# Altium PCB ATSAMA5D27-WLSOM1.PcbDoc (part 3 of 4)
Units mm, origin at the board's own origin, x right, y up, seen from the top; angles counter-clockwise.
Board outline 40.8 x 40.8 mm, 6 copper layers (L1 - Top, L2 - GND, L3 - Signal, L4 - Signal, L5 - PWR, L6 - Bottom), stack 1.144 mm thick; 196 components, 221 nets, 1038 pads, 713 vias.
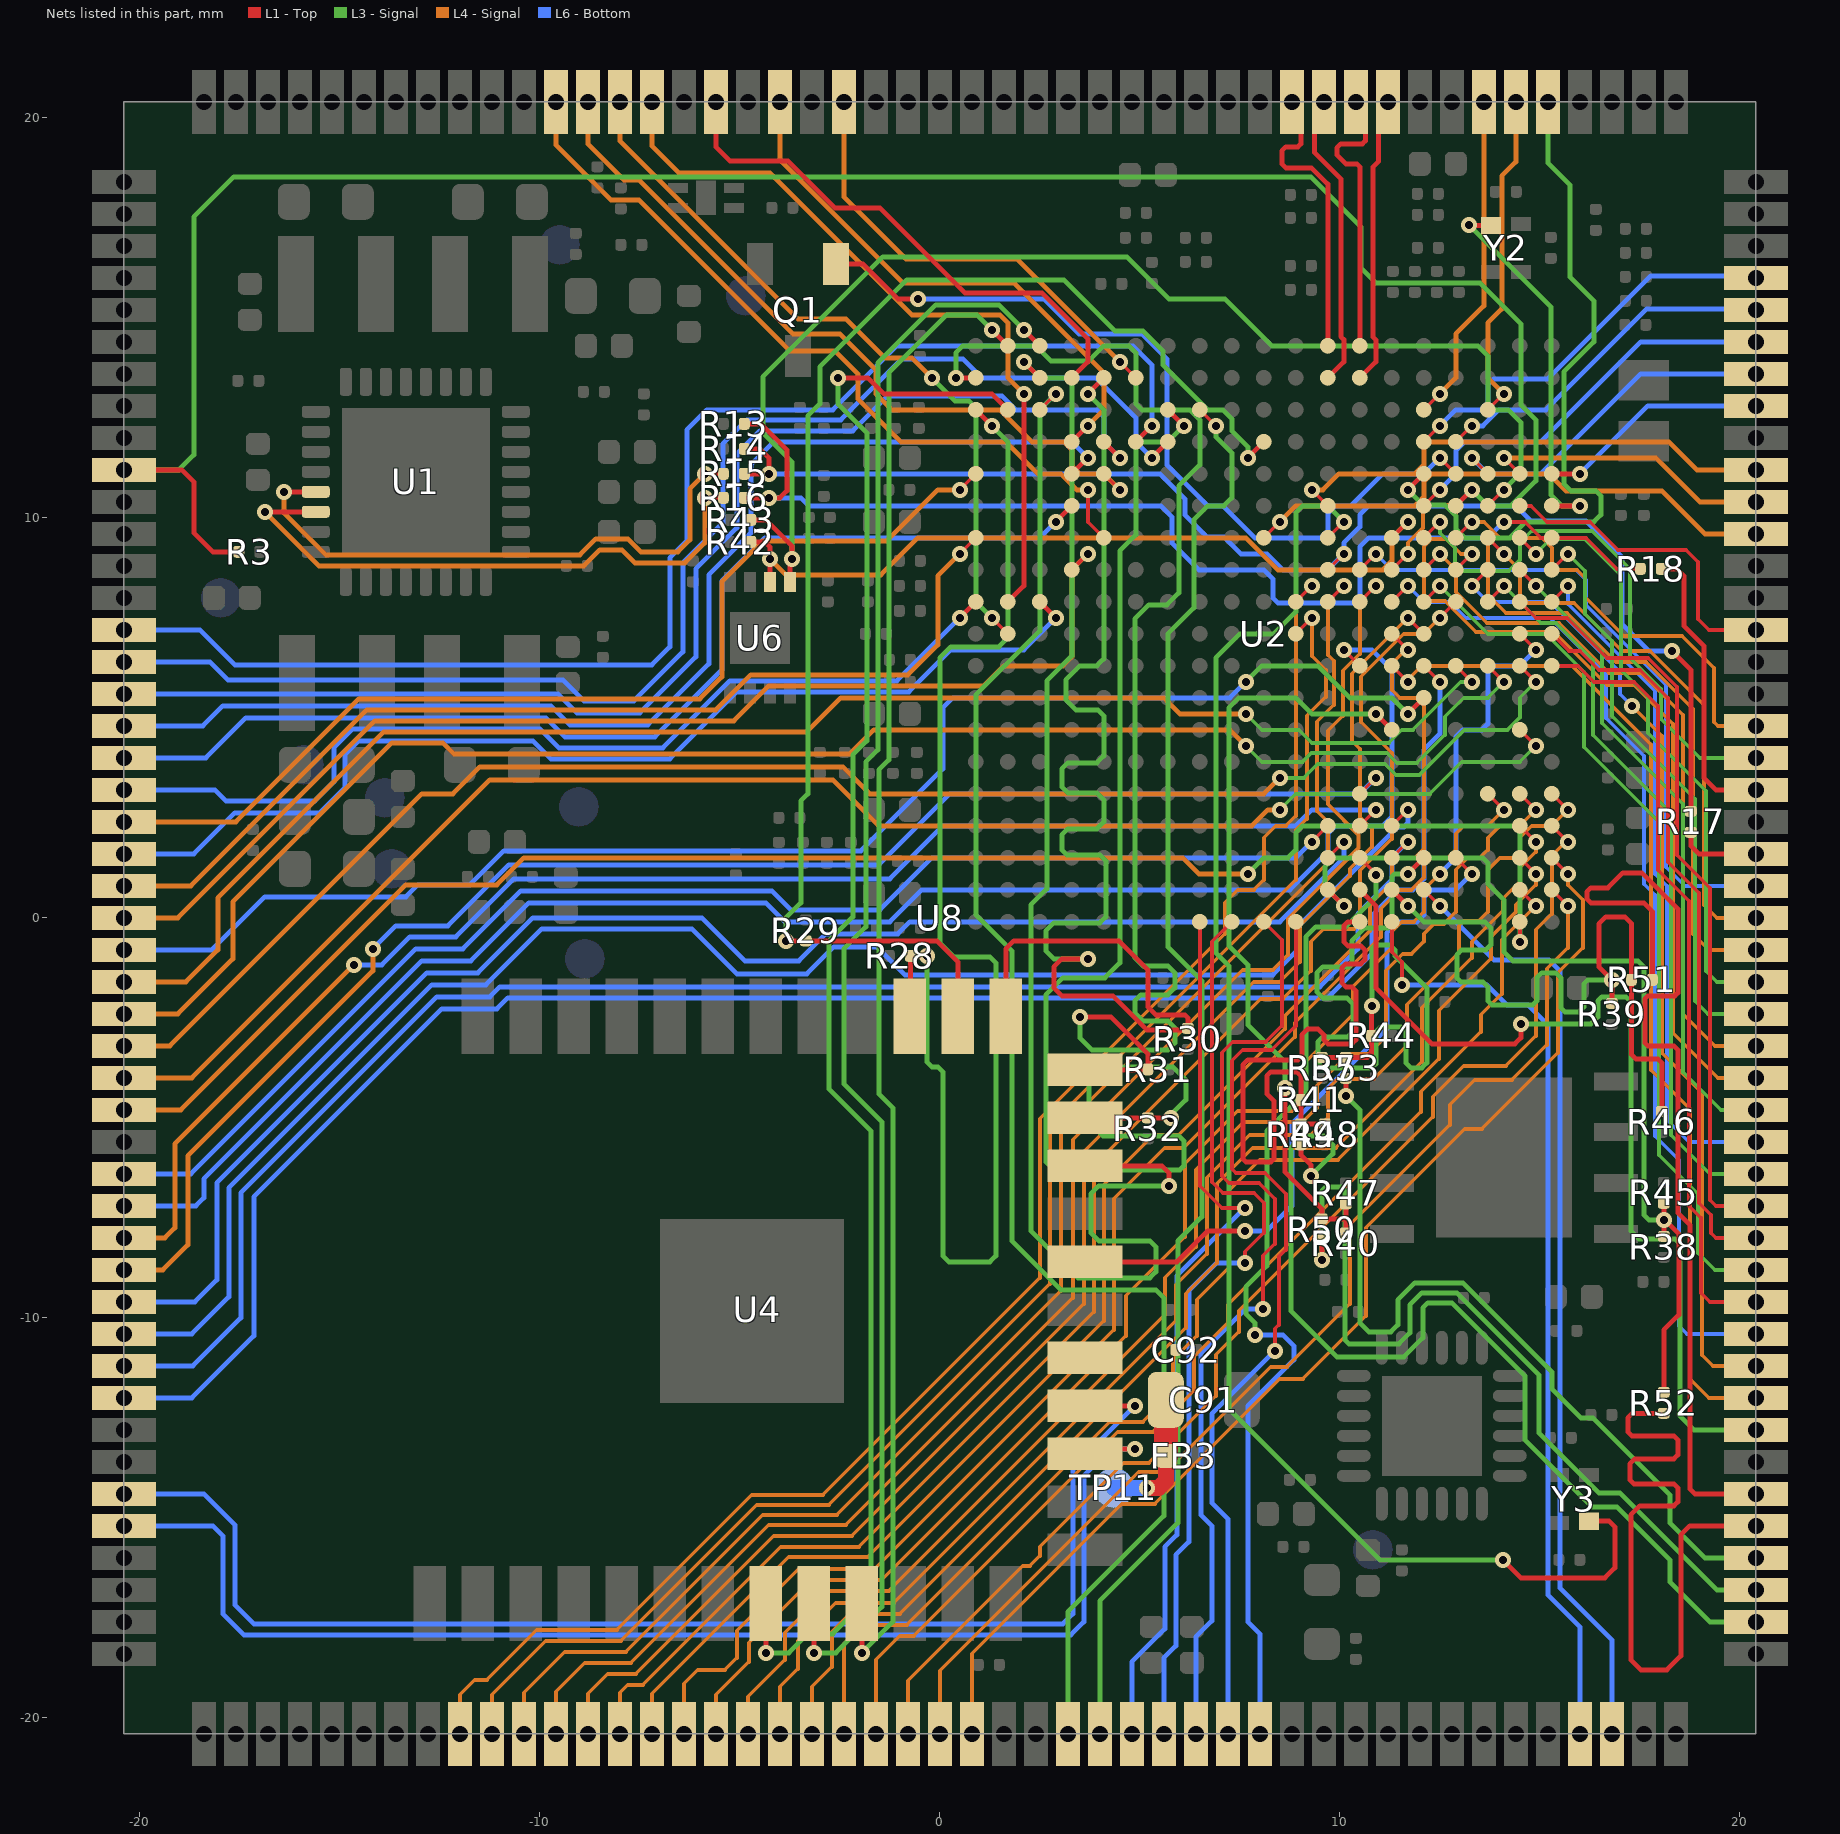
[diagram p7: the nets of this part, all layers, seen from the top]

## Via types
v1: diameter 0.4, hole 0.2, L1 - Top to L6 - Bottom, 680 vias
v2: diameter 0.4, hole 0.2, L1 - Top to L6 - Bottom, tented both sides, 17 vias
v3: diameter 0.4, hole 0.2, L1 - Top to L6 - Bottom, tented bottom, 16 vias

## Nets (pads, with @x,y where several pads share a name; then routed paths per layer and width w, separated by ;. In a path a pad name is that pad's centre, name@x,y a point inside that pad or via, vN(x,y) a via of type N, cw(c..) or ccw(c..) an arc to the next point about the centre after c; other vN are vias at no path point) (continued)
PA9: U2.V16 U8.172 | length 13.6
  L1 - Top w0.125: U8.172@-5.6,20.4 -5.6,19.275 -5.25,18.925 -3.8,18.925 -2.625,17.75 -1.5,17.75 0.625,15.625 2.55,15.625 3.7,14.475 3.7,13.9 U2.V16@3.3,13.5
PA10: U2.V14 U8.168 | length 11.5
  L1 - Top w0.1: v1(4.5,13.9) U2.V14@4.9,13.5
  L4 - Signal w0.125: U8.168@-2.4,20.4 -2.4,18.025 -0.85,16.475 1.925,16.475 v1(4.5,13.9)
PA11: U2.L18 U8.174 | length 19.1
  L1 - Top w0.125: U2.L18@1.7,7.9 2.1,8.3 v1(2.1,13.1)
  L4 - Signal w0.125: U8.174@-7.2,20.35 -7.2,19.3 -6.525,18.625 -4.25,18.625 -0.7,15.075 1.5,15.075 1.7,14.875 1.7,13.5 v1(2.1,13.1)
PA12: U2.T16 U8.170 | length 13.8
  L1 - Top w0.125: U2.T16@3.3,11.9 v1(3.7,12.3)
  L4 - Signal w0.125: U8.170@-4,20.4 -4,18.95 -0.925,15.875 1.85,15.875 4.1,13.625 4.1,12.7 v1(3.7,12.3)
PA13: U2.K18 U8.175 | length 18.6
  L1 - Top w0.1: v1(1.3,7.5) U2.K18@1.7,7.1
  L3 - Signal w0.125: v1(-0.2,13.5) 0.375,12.925 0.725,12.925 0.9,12.75 0.9,7.9 v1(1.3,7.5)
  L4 - Signal w0.125: U8.175@-8,20.4 -8,19.425 -3.55,14.975 -2.35,14.975 -1.375,14 -0.7,14 v1(-0.2,13.5)
PA14: U2.R19 U8.21 | length 26.3
  L1 - Top w0.1: v1(0.5,10.7) U2.R19@0.9,11.1
  L4 - Signal w0.125: U8.21@-20.4,2.4 -17.6,2.4 -14.525,5.475 -6,5.475 -5.45,6.025 -5.45,8.4 -4.425,9.425 -1.325,9.425 -0.05,10.7 v1(0.5,10.7)
PA15: U2.L17 U8.22 | length 27.2
  L1 - Top w0.125: U2.L17@2.5,7.9 v1(2.9,7.5)
  L6 - Bottom w0.125: U8.22@-20.4,1.6 -18.65,1.6 -17.625,2.625 -15.5,2.625 -14.875,3.25 -14.875,4.075 -14.525,4.425 -10.175,4.425 -9.725,3.975 -6.75,3.975 -5.075,5.65 -0.775,5.65 0.275,6.7 2.1,6.7 v1(2.9,7.5)
PA16: U2.N19 U8.23 | length 25.9
  L1 - Top w0.1: v1(0.5,9.1) U2.N19@0.9,9.5
  L4 - Signal w0.125: U8.23@-20.4,0.8 -18.725,0.8 -14.325,5.2 -5.6,5.2 -4.725,6.075 -0.8,6.075 -0.05,6.825 -0.05,8.55 v1(0.5,9.1)
PA17: U2.M16 U8.24 | length 29.7
  L1 - Top w0.1: U2.M16@3.3,8.7 v1(3.7,9.1)
  L4 - Signal w0.125: U8.24@-20.4,0 -19.05,0 -14.125,4.925 -5.15,4.925 -4.275,5.8 1.1,5.8 1.6,6.3 3.075,6.3 3.3,6.525 3.3,8.7 v1(3.7,9.1)
PA30: U2.U12 U8.76 | length 35.7
  L1 - Top w0.1: U2.U12@6.5,12.7 v1(6.9,12.3)
  L3 - Signal w0.125: U8.76@4,-20.4 4,-17.075 5.95,-15.125 5.95,-8.075 6.55,-7.475 6.55,-1.575 5.7,-0.725 5.7,7.1 6.35,7.75 6.35,9.95 6.7,10.3 7.1,10.3 7.3,10.5 7.3,11.625 6.9,12.025 v1(6.9,12.3)
PA31: U2.U17 U8.75 | length 39.2
  L1 - Top w0.1: U2.U17@2.5,12.7 v1(2.9,13.1)
  L3 - Signal w0.125: v1(2.9,13.1) 2.5,12.7 2.5,7.175 0.9,5.575 0.9,0.075 1.8,-0.825 1.8,-8.075 3.025,-9.3 5.4,-9.3 5.6,-9.5 5.6,-14.95 3.2,-17.35 U8.75@3.2,-20.4
PB0: U2.C7 U8.81 | length 25.4
  L1 - Top w0.1: U2.C7@10.5,1.5 10.9,1.1 v1(10.9,1.075)
  L3 - Signal w0.125: v1(7.875,-10.425) 7.875,-10.125 7.65,-9.9 7.65,-9.225 8.175,-8.7 8.175,-5.325 9.15,-4.35 9.15,-0.475 9.4,-0.225 10.15,-0.225 10.9,0.525 v1(10.9,1.075)
  L6 - Bottom w0.125: v1(7.875,-10.425) 8.575,-10.425 8.85,-10.7 8.85,-11.05 7.7,-12.2 7.7,-17.6 8,-17.9 U8.81@8,-20.4
PB1: U2.A9 U8.80 | length 23.3
  L1 - Top w0.1: v1(8.375,-10.825) 8.375,-10.275 8.475,-10.175 8.475,-8.475 8.65,-8.3 8.65,-6.9 8.125,-6.375 7.4,-6.375 7.3,-6.275 7.3,-3.575 7.575,-3.3 8.3,-3.3 8.9,-2.7 U2.A9@8.9,-0.1
  L6 - Bottom w0.125: U8.80@7.2,-20.4 7.2,-15.025 6.8,-14.625 6.8,-12.4 v1(8.375,-10.825)
PB2: U2.A10 U8.79 | length 23.9
  L1 - Top w0.1: v1(8.075,-9.775) 8.075,-8.45 8.375,-8.15 8.375,-7.025 7.975,-6.625 7.225,-6.625 7.05,-6.45 7.05,-3.375 7.325,-3.1 8.15,-3.1 8.55,-2.7 8.55,-0.55 U2.A10@8.1,-0.1
  L6 - Bottom w0.125: U8.79@6.4,-20.4 6.4,-17.975 6.8,-17.575 6.8,-15.2 6.525,-14.925 6.525,-10.9 7.65,-9.775 v1(8.075,-9.775)
PB3: U2.A11 U8.78 | length 22.9
  L1 - Top w0.1: U2.A11@7.3,-0.1 6.8,-0.6 6.8,-6.6 7.075,-6.875 7.85,-6.875 8.1,-7.125 8.1,-7.875 7.625,-8.35 v1(7.625,-8.625)
  L6 - Bottom w0.125: U8.78@5.6,-20.4 5.6,-18.5 5.9,-18.2 5.9,-15.925 6.225,-15.6 6.225,-9.325 6.925,-8.625 v1(7.625,-8.625)
PB4: U2.A12 U8.77 | length 22.3
  L1 - Top w0.1: U2.A12@6.5,-0.1 6.5,-0.617 6.5,-6.7 7.05,-7.25 v1(7.625,-7.25)
  L6 - Bottom w0.125: U8.77@4.8,-20.4 4.8,-18.6 5.625,-17.775 5.625,-15.725 5.925,-15.425 5.925,-8.95 v1(7.625,-7.25)
PB11: U2.B5 U8.92 | length 23.9
  L1 - Top w0.1: U2.B5@12.1,0.7 v1(12.5,0.3)
  L6 - Bottom w0.125: v1(12.5,0.3) 13.85,-1.05 15.225,-1.05 15.5,-1.325 15.5,-16.75 16.8,-18.05 U8.92@16.8,-20.4
PB12: U2.A6 U8.91 | length 23.8
  L1 - Top w0.1: U2.A6@11.3,-0.1 11.3,-0.85 11.55,-1.1 v1(11.55,-1.675)
  L6 - Bottom w0.125: v1(11.55,-1.675) 13.675,-1.675 14.175,-2.175 14.7,-2.175 15.2,-2.675 15.2,-16.925 16,-17.725 U8.91@16,-20.4
PB26: U2.G2 U8.29 | length 40.3
  L1 - Top w0.1: U2.G2@14.5,4.7 v1(14.9,4.3)
  L3 - Signal w0.1: v1(8.5,2.7) 8.9,3.1 12.25,3.1 13.05,3.9 14.5,3.9 v1(14.9,4.3)
  L4 - Signal w0.125: U8.29@-20.4,-4 -18.7,-4 -11.25,3.45 -2.675,3.45 -1.525,2.3 7.8,2.3 8.2,2.7 v1(8.5,2.7)
PB27: U2.H5 U8.25 | length 37
  L1 - Top w0.125: v1(11.7,5.1) U2.H5@12.1,5.5
  L3 - Signal w0.125: v1(7.65,5.9) 8.05,6.3 9.45,6.3 10.25,5.5 11.3,5.5 v1(11.7,5.1)
  L6 - Bottom w0.125: U8.25@-20.4,-0.8 -18.2,-0.8 -16.875,0.525 -13.35,0.525 -13.05,0.825 -11.75,0.825 -10.9,1.675 -1.975,1.675 0.075,3.725 0.075,5.25 0.325,5.5 7.25,5.5 v1(7.65,5.9)
PB28: U2.J2 U8.28 | length 40.7
  L1 - Top w0.1: U2.J2@14.5,6.3 v1(14.9,5.9)
  L3 - Signal w0.1: v1(8.5,3.5) 9.1,3.5 9.45,3.85 11.125,3.85 11.4,3.575 11.992,3.575 13.117,4.7 14.195,4.7 14.5,5.005 14.5,5.5 v1(14.9,5.9)
  L4 - Signal w0.125: U8.28@-20.4,-3.2 -19.25,-3.2 -12.95,3.1 -12.175,3.1 -11.5,3.775 -2.425,3.775 -1.75,3.1 8.1,3.1 v1(8.5,3.5)
PB29: U2.J3 U8.27 | length 40.7
  L1 - Top w0.1: U2.J3@13.7,6.3 v1(14.1,5.9)
  L3 - Signal w0.1: v1(7.65,4.3) 8.05,3.9 9.067,3.9 9.292,4.125 11.175,4.125 11.425,3.875 11.925,3.875 12.625,4.575 12.625,5.025 13.1,5.5 13.7,5.5 v1(14.1,5.9)
  L4 - Signal w0.125: U8.27@-20.4,-2.4 -19.05,-2.4 -17.675,-1.025 -17.675,0.4 -13.7,4.375 -12.425,4.375 -12.15,4.1 -2.25,4.1 -1.65,4.7 7.25,4.7 v1(7.65,4.3)
PB30: U2.A2 U8.30 | length 41.8
  L1 - Top w0.1: v1(14.5,-0.6) U2.A2@14.5,-0.1
  L3 - Signal w0.125: v1(7.7,1.1) 8.1,1.5 8.7,1.5 8.9,1.7 8.9,2.125 9.075,2.3 14.325,2.3 14.5,2.125 v1(14.5,-0.6)
  L4 - Signal w0.125: U8.30@-20.4,-4.8 -18.975,-4.8 -13.35,0.825 -11.075,0.825 -10.4,1.5 6.075,1.5 6.475,1.1 v1(7.7,1.1) v1@7.75,1.1
PB31: U2.J4 U8.26 | length 39.1
  L1 - Top w0.1: U2.J4@12.9,6.3 v1(13.3,5.9)
  L3 - Signal w0.1: v1(7.65,5.1) 8.05,4.7 8.975,4.7 9.3,4.375 11.225,4.375 11.55,4.7 11.825,4.7 13.025,5.9 v1(13.3,5.9)
  L4 - Signal w0.125: U8.26@-20.4,-1.6 -18.85,-1.6 -18.05,-0.8 -18.05,0.5 -13.9,4.65 -3.325,4.65 -2.475,5.5 5.6,5.5 6,5.1 v1(7.65,5.1)
PC0: U2.T14 U8.15 | length 34.6
  L1 - Top w0.125: U2.T14@4.9,11.9 v1(5.3,12.3)
  L6 - Bottom w0.125: U8.15@-20.4,7.2 -18.5,7.2 -17.625,6.325 -7.2,6.325 -6.75,6.775 -6.75,9 -6.325,9.425 -6.325,12.2 -5.825,12.7 -2.675,12.7 -1.075,14.3 4.825,14.3 5.3,13.825 v1(5.3,12.3)
PC1: U2.R16 U8.18 | length 30.7
  L1 - Top w0.125: U2.R16@3.3,11.1 v1(3.7,11.5)
  L6 - Bottom w0.125: U8.18@-20.2,5 U8.18@-20.4,4.8 -18.425,4.8 -17.925,5.3 -9.725,5.3 -9.25,4.825 -7.3,4.825 -5.775,6.35 -5.775,8.575 -4.725,9.625 -4.725,11.325 -4.15,11.9 3.3,11.9 v1(3.7,11.5)
PC2: U2.T15 U8.17 | length 32.3
  L1 - Top w0.125: U2.T15@4.1,11.9 v1(4.5,11.5)
  L6 - Bottom w0.125: U8.17@-20.4,5.6 -9.55,5.6 -9.075,5.125 -7.5,5.125 -6.1,6.525 -6.1,8.725 -5.075,9.75 -5.075,11.6 -4.5,12.175 -2.175,12.175 -1.3,13.05 1.55,13.05 1.9,12.7 3.925,12.7 4.1,12.525 4.1,11.9 v1(4.5,11.5)
PC3: U2.T13 U8.16 | length 34
  L1 - Top w0.125: v1(5.3,11.5) U2.T13@5.7,11.9
  L6 - Bottom w0.125: U8.16@-20.4,6.4 -18.25,6.4 -17.8,5.95 -9.425,5.95 -8.9,5.425 -7.65,5.425 -6.425,6.65 -6.425,8.875 -5.425,9.875 -5.425,11.85 -4.825,12.45 -2.475,12.45 -0.95,13.975 0.575,13.975 1.05,13.5 3.9,13.5 4.9,12.5 4.9,11.9 v1(5.3,11.5)
PC4: U2.P16 U8.19 | length 28
  L1 - Top w0.125: v1(2.9,9.9) U2.P16@3.3,10.3
  L6 - Bottom w0.125: U8.19@-20.4,4 -18.35,4 -17.35,5 -9.85,5 -9.375,4.525 -7.125,4.525 -5.45,6.2 -5.45,8.425 -4.375,9.5 2.5,9.5 v1(2.9,9.9)
PC5: U2.L19 U8.20 | length 24.4
  L1 - Top w0.125: v1(0.5,7.5) U2.L19@0.9,7.9
  L6 - Bottom w0.125: U8.20@-20.4,3.2 -18.125,3.2 -17.85,2.925 -15.625,2.925 -15.15,3.4 -15.15,4.25 -14.675,4.725 -10,4.725 -9.525,4.25 -6.925,4.25 -5.25,5.925 -1.075,5.925 v1(0.5,7.5)
PC6: U2.R15 U8.176 | length 19.1
  L1 - Top w0.1: U2.R15@4.1,11.1 v1(4.5,10.7)
  L4 - Signal w0.125: U8.176@-8.8,20.4 -8.8,19.35 -7.9,18.45 -7.525,18.45 -3.675,14.6 -2.5,14.6 -1.6,13.7 -1.6,13.1 -1.2,12.7 1.5,12.7 2.3,11.9 3.1,11.9 3.3,11.7 3.3,11.3 3.5,11.1 4.1,11.1 v1(4.5,10.7)
PC7: U2.N15 U8.177 | length 19.7
  L1 - Top w0.1: v1(3.7,10.7) 3.7,9.9 U2.N15@4.1,9.5
  L4 - Signal w0.125: U8.177@-9.6,20.4 -9.6,19.325 -8.225,17.95 -7.525,17.95 -3.75,14.175 -2.625,14.175 -2.05,13.6 -2.05,12.975 -0.975,11.9 1.65,11.9 2.45,11.1 3.025,11.1 3.425,10.7 v1(3.7,10.7)
PC9: U2.B2 U8.69 | length 28.8
  L1 - Top w0.1: U2.B2@14.5,0.7 v1(14.9,0.3)
  L4 - Signal w0.1: U8.69@-1.6,-20.4 -1.6,-18.55 -1,-17.95 -0.65,-17.95 4.45,-12.85 5.325,-12.85 6.35,-11.825 6.35,-10.975 7.2,-10.125 7.2,-9.675 12.025,-4.85 12.025,-4.35 13.525,-2.85 13.525,-2.425 14.05,-1.9 14.05,-0.55 v1(14.9,0.3)
PC10: U2.K5 U8.60 | length 39.3
  L1 - Top w0.1: v1(11.7,7.5) U2.K5@12.1,7.1
  L4 - Signal w0.1: U8.60@-8.8,-20.4 -8.8,-19.4 -8.3,-18.9 -7.6,-18.9 -4.15,-15.45 -2.2,-15.45 3.6,-9.65 3.6,-5.85 7.85,-1.6 8.5,-1.6 9,-1.1 9,-0.2 10.25,1.05 10.25,1.225 10.8,1.775 10.8,2.225 10.5,2.525 10.5,4.225 10.3,4.425 10.3,6.1 v1(11.7,7.5)
PC11: U2.C2 U8.68 | length 31.5
  L1 - Top w0.1: U2.C2@14.5,1.5 v1(14.9,1.1)
  L4 - Signal w0.1: U8.68@-2.4,-20.4 -2.4,-18.15 -1.925,-17.675 -0.825,-17.675 4.25,-12.6 5.075,-12.6 5.825,-11.85 5.825,-11.05 6.425,-10.45 6.425,-9.55 7.225,-8.75 7.225,-6.825 8,-6.05 9.95,-6.05 12.475,-3.525 12.475,-2.325 13.775,-1.025 13.775,-0.486 14.4,0.139 14.4,0.325 14.9,0.825 v1(14.9,1.1)
PC12: U2.D2 U8.67 | length 32.3
  L1 - Top w0.1: U2.D2@14.5,2.3 v1(14.9,1.9)
  L4 - Signal w0.1: U8.67@-3.2,-20.4 -3.2,-19.225 -2.7,-18.725 -2.7,-17.85 -2.25,-17.4 -1,-17.4 6.15,-10.25 6.15,-9.4 6.925,-8.625 6.925,-6.65 7.825,-5.75 9.9,-5.75 12.05,-3.6 12.05,-2.25 13.3,-1 13.3,-0.6 14.075,0.175 14.075,0.475 14.5,0.9 14.5,1.25 14.9,1.65 v1(14.9,1.9)
PC13: U2.K2 U8.64 | length 38.8
  L1 - Top w0.1: U2.K2@14.5,7.1 v1(14.9,6.7)
  L4 - Signal w0.1: U8.64@-5.6,-20.4 -5.6,-19.425 -4.775,-18.6 -4.775,-18.125 -3.2,-16.55 -1.45,-16.55 4.65,-10.45 4.65,-9.45 6.125,-7.975 6.125,-6.15 7.45,-4.825 8.8,-4.825 9.15,-4.475 9.15,-3.6 10.325,-2.425 10.325,-1.725 11.3,-0.75 11.3,-0.35 11.55,-0.1 11.85,-0.1 12.1,0.15 12.1,0.7 v1(12.5,1.1)
  L6 - Bottom w0.125: v1(12.5,1.1) 12.9,1.5 12.9,4.525 13.075,4.7 13.55,4.7 13.7,4.85 13.7,6.175 13.825,6.3 14.5,6.3 v1(14.9,6.7)
PC14: U2.K6 U8.62 | length 38.2
  L1 - Top w0.1: U2.K6@11.3,7.1 v1(11.7,6.7)
  L4 - Signal w0.1: U8.62@-7.2,-20.4 -7.2,-19.4 -3.775,-15.975 -1.8,-15.975 4.1,-10.075 4.1,-6.675 5.35,-5.425 5.975,-5.425 8.625,-2.775 8.625,-2.459 10.75,-0.334 10.75,0.325 11.3,0.875 11.3,1.375 11.425,1.5 11.875,1.5 12.1,1.725 12.1,5.3 11.9,5.5 11.5,5.5 11.3,5.7 11.3,6.35 11.65,6.7 v1(11.7,6.7)
PC15: U2.B1 U8.71 | length 28.9
  L1 - Top w0.1: U2.B1@15.3,0.7 v1(15.7,0.3)
  L4 - Signal w0.1: U8.71@0,-20.4 0,-18.825 4.975,-13.85 5.65,-13.85 8.275,-11.225 8.675,-11.225 10.25,-9.65 10.25,-7.675 12.75,-5.175 12.75,-4.675 13.375,-4.05 14.3,-4.05 15.175,-3.175 15.175,-1.275 15.7,-0.75 v1(15.7,0.3)
PC16: U2.K9 U8.57 | length 39.4
  L1 - Top w0.1: U2.K9@8.9,7.1 v1(9.3,7.5)
  L4 - Signal w0.1: U8.57@-11.2,-20.4 -11.2,-19.425 -9.85,-18.075 -7.975,-18.075 -4.575,-14.675 -2.775,-14.675 2.75,-9.15 2.75,-5.2 8.9,0.95 8.9,2.2 9.175,2.475 9.175,5.05 9.65,5.525 9.65,6.2 9.3,6.55 v1(9.3,7.5)
PC17: U2.C1 U8.72 | length 29.6
  L1 - Top w0.1: U2.C1@15.3,1.5 v1(15.7,1.1)
  L4 - Signal w0.1: U8.72@0.8,-20.4 0.8,-18.4 4.55,-14.65 5.375,-14.65 8.5,-11.525 9.075,-11.525 10.65,-9.95 10.65,-7.75 13.125,-5.275 13.55,-5.275 15.45,-3.375 15.45,-1.375 16.075,-0.75 16.075,0.45 15.7,0.825 v1(15.7,1.1)
PC18: U2.L9 U8.56 | length 40.9
  L1 - Top w0.1: U2.L9@8.9,7.9 v1(9.3,8.3)
  L4 - Signal w0.1: U8.56@-12,-20.4 -12,-19.425 -11.625,-19.05 -11.325,-19.05 -10.075,-17.8 -8.075,-17.8 -4.7,-14.425 -2.925,-14.425 2.5,-9 2.5,-5.025 7.125,-0.4 7.125,0.375 7.45,0.7 7.85,0.7 8.1,0.95 8.1,2 8.4,2.3 8.65,2.3 8.9,2.55 8.9,7.9 v1(9.3,8.3)
PC19: U2.D1 U8.70 | length 30.8
  L1 - Top w0.1: U2.D1@15.3,2.3 v1(15.7,1.9)
  L4 - Signal w0.1: U8.70@-0.8,-20.4 -0.8,-19.075 2.075,-16.2 2.25,-16.2 2.5,-15.95 2.5,-15.725 4.6,-13.625 5.225,-13.625 6.9,-11.95 6.9,-10.925 7.475,-10.35 7.475,-9.825 12.325,-4.975 12.325,-4.475 13.1,-3.7 14.15,-3.7 14.9,-2.95 14.9,-0.3 15.3,0.1 15.3,1.55 15.65,1.9 v1(15.7,1.9)
PC20: U2.L8 U8.58 | length 40.1
  L1 - Top w0.1: U2.L8@9.7,7.9 v1(10.1,8.3)
  L4 - Signal w0.1: U8.58@-10.4,-20.4 -10.4,-19.375 -9.375,-18.35 -7.85,-18.35 -4.425,-14.925 -2.575,-14.925 3.025,-9.325 3.025,-5.3 9.7,1.375 9.7,2.4 9.425,2.675 9.425,4.9 9.85,5.325 9.85,6.425 9.7,6.575 9.7,7.9 v1(10.1,8.3)
PC21: U2.E3 U8.63 | length 34.7
  L1 - Top w0.1: U2.E3@13.7,3.1 v1(14.1,2.7)
  L4 - Signal w0.1: U8.63@-6.4,-20.4 -6.4,-19.15 -6.05,-18.8 -5.375,-18.8 -5.075,-18.5 -5.075,-17.825 -3.525,-16.275 -1.625,-16.275 4.35,-10.3 4.35,-7.025 5.625,-5.75 6.1,-5.75 8.875,-2.975 8.875,-2.625 11.025,-0.475 11.025,0.225 11.5,0.7 11.795,0.7 12.1,1.005 12.1,1.3 12.3,1.5 12.7,1.5 12.9,1.7 12.9,2.1 13.1,2.3 13.7,2.3 v1(14.1,2.7)
PC22: U2.E2 U8.65 | length 34.6
  L1 - Top w0.1: U2.E2@14.5,3.1 v1(14.9,2.7)
  L4 - Signal w0.1: U8.65@-4.8,-20.4 -4.8,-19.475 -3.875,-18.55 -3.875,-17.875 -2.825,-16.825 -1.275,-16.825 5.625,-9.925 5.625,-9 6.4,-8.225 6.4,-6.3 7.6,-5.1 9.075,-5.1 9.425,-4.75 9.425,-4.2 10.225,-3.4 10.725,-3.4 11.15,-2.975 11.15,-1.325 11.575,-0.9 11.795,-0.9 12.1,-0.595 12.1,-0.405 12.355,-0.15 12.6,-0.15 12.9,0.15 12.9,1.2 13.2,1.5 13.5,1.5 13.7,1.7 13.7,1.995 14.005,2.3 14.5,2.3 v1(14.9,2.7)
PC23: U2.L7 U8.59 | length 40.6
  L1 - Top w0.1: U2.L7@10.5,7.9 v1(10.9,8.3)
  L4 - Signal w0.1: U8.59@-9.6,-20.4 -9.6,-19.35 -8.875,-18.625 -7.725,-18.625 -4.275,-15.175 -2.35,-15.175 3.325,-9.5 3.325,-5.55 7.575,-1.3 8.334,-1.3 8.7,-0.934 8.7,-0.025 10.467,1.742 10.467,2.072 9.7,2.839 9.7,4.675 10.075,5.05 10.075,6.175 10.5,6.6 10.5,7.9 v1(10.9,8.3)
PC24: U2.E1 U8.66 | length 34.8
  L1 - Top w0.1: U2.E1@15.3,3.1 v1(15.7,2.7)
  L4 - Signal w0.1: U8.66@-4,-20.4 -4,-19.225 -3.55,-18.775 -3.55,-18.075 -2.6,-17.125 -1.15,-17.125 5.9,-10.075 5.9,-9.175 6.675,-8.4 6.675,-6.5 7.75,-5.425 9.275,-5.425 9.7,-5 9.7,-4.275 9.95,-4.025 10.85,-4.025 11.675,-3.2 11.675,-2.175 12.975,-0.875 12.975,-0.2 13.1,-0.075 13.475,-0.075 13.7,0.15 13.7,1.195 14.005,1.5 14.325,1.5 14.5,1.675 14.5,2 14.8,2.3 15.3,2.3 v1(15.7,2.7)
PC25: U2.L4 U8.61 | length 40
  L1 - Top w0.1: v1(12.5,7.5) U2.L4@12.9,7.9
  L4 - Signal w0.1: U8.61@-8,-20.4 -8,-19.375 -7.8,-19.175 -7.425,-19.175 -3.975,-15.725 -2.025,-15.725 3.85,-9.85 3.85,-6.2 8.025,-2.025 8.575,-2.025 9.275,-1.325 9.275,-0.6 9.6,-0.275 10.35,-0.275 10.5,-0.125 10.5,1.175 11.3,1.975 11.3,4.125 10.525,4.9 10.525,6.025 11.6,7.1 12.1,7.1 v1(12.5,7.5)
PC26: U2.D6 U8.37 | length 41.7
  L1 - Top w0.1: U2.D6@11.3,2.3 v1(11.7,2.7)
  L6 - Bottom w0.125: U8.37@-20.4,-10.4 -18.7,-10.4 -17.775,-9.475 -17.775,-6.75 -12.7,-1.675 -11.35,-1.675 -9.95,-0.275 -6.2,-0.275 -5.075,-1.4 -3.325,-1.4 -2.65,-0.725 -1.575,-0.725 -0.875,-1.425 8.325,-1.425 8.925,-0.825 8.925,-0.25 11.45,2.275 11.6,2.275 11.7,2.375 v1(11.7,2.7)
PC27: U2.E7 U8.35 | length 38.6
  L1 - Top w0.1: U2.E7@10.5,3.1 v1(10.9,3.5)
  L4 - Signal w0.125: U8.35@-20.4,-8.8 -19.425,-8.8 -18.8,-8.175 -18.8,-5.95 -14.175,-1.325 v1(-14.175,-0.775)
  L6 - Bottom w0.125: v1(-14.175,-0.775) -13.6,-0.2 -12.3,-0.2 -10.775,1.325 -1.525,1.325 0.25,3.1 10.5,3.1 v1(10.9,3.5)
PC28: U2.J5 U8.39 | length 46.1
  L1 - Top w0.1: U2.J5@12.1,6.3 v1(12.5,5.9)
  L6 - Bottom w0.125: U8.39@-20.4,-12 -18.7,-12 -17.15,-10.45 -17.15,-6.975 -12.45,-2.275 -11.075,-2.275 -10.8,-2 9.7,-2 10.8,-0.9 10.8,0.05 11.45,0.7 11.825,0.7 12.1,0.975 12.1,4.2 12.5,4.6 v1(12.5,5.9)
PC29: U2.C6 U8.38 | length 40.8
  L1 - Top w0.1: U2.C6@11.3,1.5 v1(11.7,1.9)
  L6 - Bottom w0.125: U8.38@-20.4,-11.2 -18.675,-11.2 -17.475,-10 -17.475,-6.875 -12.575,-1.975 -11.25,-1.975 -11,-1.725 9.5,-1.725 10.45,-0.775 10.45,0.1 11.3,0.95 11.3,1.5 v1(11.7,1.9)
PC30: U2.D7 U8.34 | length 37.5
  L1 - Top w0.1: U2.D7@10.5,2.3 v1(10.9,2.7)
  L4 - Signal w0.125: U8.34@-20.4,-8 -19.375,-8 -19.125,-7.75 -19.125,-5.65 v1(-14.65,-1.175)
  L6 - Bottom w0.125: v1(-14.65,-1.175) -13.95,-1.175 -13.25,-0.475 -12.1,-0.475 -10.65,0.975 -1.25,0.975 0.075,2.3 8.9,2.3 9.3,2.7 v1(10.9,2.7)
PC31: U2.C8 U8.36 | length 38.4
  L1 - Top w0.1: U2.C8@9.7,1.5 v1(10.1,1.9)
  L6 - Bottom w0.125: U8.36@-20.4,-9.6 -18.625,-9.6 -18.075,-9.05 -18.075,-6.625 -12.825,-1.375 -11.55,-1.375 -10.175,0 -5.95,0 -4.875,-1.075 -3.525,-1.075 -2.85,-0.4 -1.05,-0.4 -0.75,-0.1 8.5,-0.1 10.1,1.5 v1(10.1,1.9)
PD0: U2.J7 U8.33 | length 42.3
  L1 - Top w0.1: v1(10.1,6.7) U2.J7@10.5,6.3
  L6 - Bottom w0.125: U8.33@-20.4,-7.2 -18.6,-7.2 -18.4,-7 -18.4,-6.525 -12.95,-1.075 -11.725,-1.075 -10.275,0.375 -4.35,0.375 -3.875,-0.1 -1.25,-0.1 -0.45,0.7 8.75,0.7 9.7,1.65 9.7,2.1 9.9,2.3 11.075,2.3 11.3,2.525 11.3,6.2 10.8,6.7 v1(10.1,6.7)
PD1: U2.D8 U8.32 | length 34.1
  L1 - Top w0.1: v1(9.3,1.9) U2.D8@9.7,2.3
  L6 - Bottom w0.125: U8.32@-20.4,-6.4 -18.725,-6.4 -13.1,-0.775 -11.925,-0.775 -10.475,0.675 -4.2,0.675 -3.725,0.2 -1.5,0.2 -0.2,1.5 8.9,1.5 v1(9.3,1.9)
PD2: U2.J6 U8.103 | length 25.4
  L1 - Top w0.1: U2.J6@11.3,6.3 v1(11.7,5.9)
  L4 - Signal w0.1: v1@11.7,5.95 12.05,6.3 15.805,6.3 17.775,4.33 17.775,-3.8 18.75,-4.775 18.75,-11.525 19.225,-12 U8.103@20.123,-12
PD3: U2.M3 U8.104 | length 24.5
  L1 - Top w0.1: v1(13.3,8.3) U2.M3@13.7,8.7
  L4 - Signal w0.1: v1(17.3,5.3) 18.05,4.55 18.05,-3.375 19.05,-4.375 19.05,-10.925 19.325,-11.2 U8.104@20.4,-11.2
  L6 - Bottom w0.1: v1(13.3,8.3) 13.7,7.9 15.25,7.9 17,6.15 17,5.6 v1(17.3,5.3)
PD4: U2.L6 U8.105 | length 25.5
  L1 - Top w0.1: U2.L6@11.3,7.9 v1(11.7,8.3)
  L6 - Bottom w0.1: v1(11.7,8.3) 12.1,7.9 12.75,7.9 13.15,7.5 15.25,7.5 16.65,6.1 16.65,5 17.6,4.05 17.6,0.85 17.875,0.575 17.875,-5.45 18.475,-6.05 18.475,-10.2 18.675,-10.4 U8.105@20.4,-10.4
PD5: U2.L2 U8.109 | length 19.2
  L1 - Top w0.1: U2.L2@14.5,7.9 14.9,7.5 15.675,7.5 16.675,6.5 17.7,6.5 18.425,5.775 18.425,1.575 19.25,0.75 19.25,-7.05 19.4,-7.2 U8.109@20.4,-7.2
PD6: U2.J1 U8.106 | length 19.7
  L1 - Top w0.1: U2.J1@15.3,6.3 15.95,6.3 16.35,5.9 17.35,5.9 17.95,5.3 17.95,1.2 18.725,0.425 18.725,-7.2 19.025,-7.5 19.025,-9.375 19.25,-9.6 U8.106@20.4,-9.6
PD7: U2.L5 U8.107 | length 22.4
  L1 - Top w0.1: U2.L5@12.1,7.9 v1(12.5,8.3)
  L3 - Signal w0.1: v1(12.5,8.3) 13.7,7.1 15.15,7.1 16.1,6.15 16.1,4.275 17.975,2.4 17.975,-5.925 18.95,-6.9 18.95,-8.375 19.375,-8.8 U8.107@20.4,-8.8
PD8: U2.K1 U8.108 | length 18.6
  L1 - Top w0.1: U2.K1@15.3,7.1 15.725,6.675 16,6.675 16.475,6.2 17.5,6.2 18.2,5.5 18.2,1.4 18.975,0.625 18.975,-7.125 19.275,-7.425 19.275,-7.875 19.4,-8 U8.108@20.4,-8
PD9: U2.L3 U8.110 | length 18.8
  L1 - Top w0.1: U2.L3@13.7,7.9 v1(14.1,8.3)
  L3 - Signal w0.1: v1(14.1,8.3) 15.025,7.375 15.4,7.375 16.325,6.45 16.325,4.575 18.275,2.625 18.275,-5.425 19.25,-6.4 U8.110@20.4,-6.4
PD10: U2.L1 U8.111 | length 17.4
  L1 - Top w0.1: U2.L1@15.3,7.9 v1(15.7,8.3)
  L6 - Bottom w0.1: v1(15.7,8.3) 15.7,7.85 17.875,5.675 17.875,1.1 18.175,0.8 18.175,-5.05 18.725,-5.6 U8.111@20.4,-5.6
PD11: U2.N3 U8.118 | length 13.9
  L1 - Top w0.1: U2.N3@13.7,9.5 v1(14.1,9.1)
  L4 - Signal w0.1: v1(14.1,9.1) 14.5,8.7 14.5,8.075 14.7,7.875 15.85,7.875 17.05,6.675 17.75,6.675 19.1,5.325 19.1,0.325 19.425,0 U8.118@20.4,0
PD12: U2.M7 U8.119 | length 16.5
  L1 - Top w0.1: U2.M7@10.5,8.7 v1(10.9,9.1)
  L6 - Bottom w0.1: v1(10.9,9.1) 11.3,8.7 15.9,8.7 16.15,8.45 16.15,7.825 18.15,5.825 18.15,1.275 18.625,0.8 U8.119@20.4,0.8
PD13: U2.N2 U8.116 | length 15.4
  L1 - Top w0.1: U2.N2@14.5,9.5 v1(14.9,9.1)
  L3 - Signal w0.1: v1(14.9,9.1) 15.275,9.475 16.12,9.475 17.025,8.57 17.025,6.2 17.7,5.525 17.7,4.625 19.15,3.175 19.15,-1.325 19.425,-1.6 U8.116@20.4,-1.6
PD14: U2.M6 U8.117 | length 19.1
  L1 - Top w0.1: U2.M6@11.3,8.7 v1(11.7,9.1)
  L4 - Signal w0.1: v1(11.7,9.1) 11.7,9.375 12.075,9.75 12.075,10.125 12.275,10.325 12.7,10.325 12.9,10.125 12.9,9.625 13.025,9.5 13.55,9.5 13.7,9.35 13.7,8.075 14.15,7.625 15.675,7.625 16.9,6.4 17.65,6.4 18.825,5.225 18.825,-0.4 19.225,-0.8 U8.117@20.4,-0.8
PD15: U2.M5 U8.114 | length 18.3
  L1 - Top w0.1: U2.M5@12.1,8.7 v1(12.5,9.1)
  L4 - Signal w0.1: v1(12.5,9.1) 12.9,8.7 12.9,8.15 13.675,7.375 15.475,7.375 16.725,6.125 17.525,6.125 18.575,5.075 18.575,-2.4 19.375,-3.2 U8.114@20.4,-3.2
PD16: U2.M1 U8.115 | length 14.7
  L1 - Top w0.1: U2.M1@15.3,8.7 v1(15.7,9.1)
  L3 - Signal w0.1: v1(15.7,9.1) 16.125,8.675 16.125,7.6 16.8,6.925 16.8,5.05 18.875,2.975 18.875,-2.075 19.2,-2.4 U8.115@20.4,-2.4
PD17: U2.M2 U8.112 | length 16.5
  L1 - Top w0.1: U2.M2@14.5,8.7 v1(14.9,8.3)
  L3 - Signal w0.1: v1(14.9,8.3) 16.55,6.65 16.55,4.875 18.575,2.85 18.575,-3.85 19.525,-4.8 U8.112@20.4,-4.8
PD18: U2.M4 U8.113 | length 21
  L1 - Top w0.1: U2.M4@12.9,8.7 v1(13.3,9.1)
  L4 - Signal w0.1: v1(13.3,9.1) 13.025,9.1 12.65,9.475 12.3,9.475 12.1,9.275 12.1,8.075 12.25,7.925 12.625,7.925 13.4,7.15 15.35,7.15 16.675,5.825 17.35,5.825 18.325,4.85 18.325,-2.875 19.45,-4 U8.113@20.4,-4
PD19: R14.1 R15.1 R17.1 U2.M8 | length 33.8
  L1 - Top w0.1: U2.M8@9.7,8.7 v1(10.1,9.1)
  L1 - Top w0.125: R15.1@-4.9,11.1 v1(-4.275,11.1) -4.275,11.5 -4.5,11.725 R14.1@-4.888,11.725 ; v1(18.3,6.675) 18.775,6.2 R17.1@18.775,2.662
  L6 - Bottom w0.125: v1(-4.275,11.1) 5.5,11.1 6.125,10.475 6.125,10.075 6.675,9.525 7.1,9.525 7.525,9.1 8.175,9.1 8.575,8.7 9.7,8.7 v1(10.1,9.1) 10.1,9.375 10.5,9.775 10.5,10.075 10.725,10.3 14.4,10.3 14.775,9.925 16.15,9.925 17.05,9.025 17.05,7.35 17.725,6.675 v1(18.3,6.675)
PD20: R13.1 R16.1 R18.1 U2.N1 | length 29.1
  L1 - Top w0.1: v1(14.1,9.9) 14.625,9.9 15.025,9.5 U2.N1@15.3,9.5 16.15,9.5 16.925,8.725 R18.1@17.512,8.725
  L1 - Top w0.125: R16.1@-4.888,10.5 -4,10.5 -3.825,10.675 -3.825,11.7 -4.475,12.35 R13.1@-4.888,12.35
  L6 - Bottom w0.125: v1(-4.275,10.5) -3.475,10.5 -3.275,10.3 5.525,10.3 5.8,10.025 5.8,9.375 6.475,8.7 8.1,8.7 8.325,8.475 8.325,8 8.45,7.875 10.325,7.875 10.5,8.05 10.5,9.275 10.725,9.5 13.7,9.5 v1(14.1,9.9)
PD23: U2.P1 Y2.1 | length 9.7
  L1 - Top w0.125: v1@13.24,17.31 Y2.1@13.775,17.31 ; U2.P1@15.3,10.3 v1(16,10.3)
  L3 - Signal w0.125: v1(13.225,17.325) 15.275,15.275 15.275,10.575 15.55,10.3 v1(16,10.3)
PD24: U2.N8 Y3.1 | length 39.1
  L1 - Top w0.1: U2.N8@9.7,9.5 v1(10.1,9.9)
  L1 - Top w0.125: v1(14.075,-16.05) 14.525,-16.5 16.625,-16.5 16.875,-16.25 16.875,-15.225 16.735,-15.085 Y3.1@16.225,-15.085
  L3 - Signal w0.125: v1(10.1,9.9) 9.7,10.3 9.075,10.3 8.9,10.125 8.9,7.65 8.35,7.1 7.5,7.1 6.9,6.5 6.9,-0.875 7.225,-1.2 7.225,-12.275 11,-16.05 v1(14.075,-16.05)
PD25: U2.P8 U8.132 | length 12.4
  L1 - Top w0.1: v1(9.3,10.7) U2.P8@9.7,10.3 U2.P8@9.7,10.35
  L4 - Signal w0.125: v1(9.3,10.7) 9.575,10.7 9.975,11.1 11.875,11.1 12.1,11.325 12.1,11.725 12.275,11.9 18.225,11.9 18.925,11.2 U8.132@20.111,11.2
PD26: U2.P2 U8.127 | length 8
  L1 - Top w0.1: U2.P2@14.5,10.3 14.775,10.3 15.175,9.9 16.25,9.9 16.95,9.2 18.65,9.2 18.95,8.9 18.95,7.475 19.225,7.2 U8.127@20.4,7.2
PD27: U2.N5 U8.123 | length 14.1
  L1 - Top w0.1: U2.N5@12.1,9.5 v1(12.5,9.9)
  L3 - Signal w0.1: v1(12.5,9.9) 12.5,9.625 12.875,9.25 12.875,8.9 13.1,8.675 14.225,8.675 14.5,8.95 14.5,9.375 14.8,9.675 16.3,9.675 17.25,8.725 17.25,6.5 18.025,5.725 18.025,4.975 19,4 U8.123@20.4,4
PD28: U2.N4 U8.124 | length 11.1
  L1 - Top w0.1: U2.N4@12.9,9.5 v1(13.3,9.9)
  L4 - Signal w0.1: v1(13.3,9.9) 13.6,9.9 14,9.5 15.05,9.5 15.3,9.25 15.3,8.825 15.425,8.7 15.925,8.7 16.125,8.5 16.125,8.025 17.1,7.05 18.55,7.05 19.35,6.25 19.35,4.9 19.45,4.8 U8.124@20.4,4.8
  L4 - Signal w0.125: U8.124@20.4,4.8 U8.124@20.425,4.8
PD29: U2.R2 U8.131 | length 7
  L1 - Top w0.1: v1(14.1,11.5) U2.R2@14.5,11.1
  L4 - Signal w0.125: v1(14.1,11.5) 17.9,11.5 19,10.4 U8.131@20.111,10.4
PD30: U2.N10 U8.130 | length 13.8
  L1 - Top w0.1: U2.N10@8.1,9.5 v1(8.5,9.9)
  L4 - Signal w0.125: v1(8.5,9.9) 8.9,10.3 11.875,10.3 12.1,10.525 12.1,10.9 12.3,11.1 15.225,11.1 15.65,10.675 18.05,10.675 19.125,9.6 U8.130@20.4,9.6
PIOBU0_PMIC: Q1.1 U2.R4 | length 21.1
  L1 - Top w0.1: v1(12.5,11.5) U2.R4@12.9,11.1
  L1 - Top w0.125: Q1.1@-2.6,16.35 -1.925,16.35 -1.05,15.475 v1(-0.55,15.475)
  L6 - Bottom w0.125: v1(-0.55,15.475) 2.6,15.475 3.475,14.6 5.05,14.6 5.675,13.975 5.675,11.325 6.7,10.3 7.075,10.3 7.875,9.5 9.525,9.5 9.7,9.675 9.7,10.1 9.9,10.3 10.275,10.3 11.075,11.1 12.1,11.1 v1(12.5,11.5)
PIOBU1: U2.R5 U8.146 | length 18.2
  L1 - Top w0.125: v1(11.7,10.7) U2.R5@12.1,11.1
  L3 - Signal w0.125: v1(11.7,10.7) 12.075,10.325 12.625,10.325 12.9,10.05 12.9,9.725 13.125,9.5 14.25,9.5 14.65,9.9 16.35,9.9 16.525,10.075 16.525,10.55 16.4,10.675 15.775,10.675 15.6,10.85 15.6,13.65 16.35,14.4 16.35,15.425 15.75,16.025 15.75,18.325 15.2,18.875 U8.146@15.2,20.4
PIOBU2: U2.R3 U8.135 | length 8.9
  L1 - Top w0.1: v1(13.3,11.5) U2.R3@13.7,11.1
  L6 - Bottom w0.125: v1(13.3,11.5) 13.7,11.1 15.025,11.1 17.525,13.6 U8.135@20.4,13.6
PIOBU3: U2.T4 U8.137 | length 8.9
  L1 - Top w0.1: U2.T4@12.9,11.9 v1(13.3,12.3)
  L6 - Bottom w0.125: v1(13.3,12.3) 13.575,12.3 13.975,12.7 15.15,12.7 17.675,15.225 20.375,15.225 U8.137@20.4,15.2
PIOBU4: U2.U3 U8.147 | length 8.3
  L1 - Top w0.1: U2.U3@13.7,12.7 v1(14.1,13.1)
  L4 - Signal w0.125: v1(14.1,13.1) 13.7,13.5 13.7,14.875 14.05,15.225 14.05,18.55 14.4,18.9 U8.147@14.4,20.4
PIOBU5: U2.T5 U8.138 | length 10.3
  L1 - Top w0.1: U2.T5@12.1,11.9 v1(12.5,12.3)
  L6 - Bottom w0.125: v1(12.5,12.3) 12.9,12.7 13.525,12.7 13.7,12.875 13.7,13.325 13.85,13.475 15.2,13.475 17.775,16.05 20.35,16.05 U8.138@20.4,16
PIOBU6: U2.U5 U8.148 | length 8.3
  L1 - Top w0.1: U2.U5@12.1,12.7 v1(12.5,13.1)
  L4 - Signal w0.125: v1(12.5,13.1) 12.9,13.5 12.9,14.6 13.6,15.3 U8.148@13.6,20.4
PIOBU7: U2.P5 U8.136 | length 10.3
  L1 - Top w0.1: U2.P5@12.1,10.3 v1(12.5,10.7)
  L6 - Bottom w0.125: v1(12.5,10.7) 12.9,11.1 12.9,11.675 13.125,11.9 15.025,11.9 17.525,14.4 U8.136@20.4,14.4
QSPI1_CS_PB6: U2.B7 U8.102 | length 23.7
  L1 - Top w0.125: U2.B7@10.5,0.7 10.9,0.3 10.9,-1.75 12.3,-3.15 14.375,-3.15 14.525,-3 v1(14.525,-2.65)
  L3 - Signal w0.125: v1(14.525,-2.65) 16.275,-2.65 16.45,-2.475 16.45,-2.075 16.55,-1.975 17.15,-1.975 17.275,-2.1 17.275,-7.825 17.475,-8.025 18.375,-8.025 18.5,-8.15 18.5,-12.45 18.85,-12.8 U8.102@20.123,-12.8
QSPI1_IO0_PB7: R37.1 R44.1 R53.1 U2.C5 | length 20.9
  L1 - Top w0.125: R37.1@9.55,-3.488 R53.1@10.15,-3.488 10.687,-3.488 10.788,-3.387 R44.1@10.788,-2.95 10.788,-2.213 v1(10.8,-2.2) ; v1(11.7,1.1) U2.C5@12.1,1.5
  L3 - Signal w0.125: v1(10.8,-2.2) 10.8,-0.775 10.9,-0.675 11.25,-0.675 11.375,-0.8 11.375,-0.95 12.175,-1.75 12.175,-3.625 12.05,-3.75 11.775,-3.75 11.65,-3.625 11.65,-2.85 11.525,-2.725 11.025,-2.725 10.9,-2.85 10.9,-3.65 10.8,-3.75 9.575,-3.75 9.45,-3.625 9.45,-3.1 9.575,-2.975 10.2,-2.975 10.325,-2.85 10.325,-2.15 10.175,-2 9.575,-2 9.425,-1.85 9.425,-1.375 9.575,-1.225 10.225,-1.225 10.3,-1.15 10.3,-0.575 10.625,-0.25 11.2,-0.25 11.3,-0.15 11.3,1.025 11.375,1.1 v1(11.7,1.1)
QSPI1_IO1_PB8: R38.1 R45.1 R52.1 U2.B8 | length 24.2
  L1 - Top w0.125: U2.B8@9.7,0.7 v1(10.1,0.3) ; R52.1@18.1,-11.863 18.1,-10.3 18.475,-9.925 18.475,-7.9 18.125,-7.55 v1(18.1,-7.55) ; R38.1@18.1,-7.963 v1(18.1,-7.55) ; R45.1@18.1,-7.137 v1(18.1,-7.55)
  L3 - Signal w0.125: v1(10.1,0.3) 9.625,0.775 9.625,1.275 9.85,1.5 13.575,1.5 13.7,1.375 13.7,0.85 14.1,0.45 14.1,-0.85 14.325,-1.075 17.45,-1.075 17.6,-1.225 17.6,-7.425 17.725,-7.55 v1(18.1,-7.55)
QSPI1_IO2_PB9: R39.1 R46.1 R51.1 U2.B6 | length 19.8
  L1 - Top w0.125: U2.B6@11.3,0.7 v1(11.7,0.3) ; R39.1@16.8,-2.138 v1(16.8,-1.55) 16.475,-1.225 16.475,-0.15 16.65,0.025 17.125,0.025 17.288,-0.138 R51.1@17.288,-1.55 17.288,-3.413 17.4,-3.525 17.95,-3.525 18.05,-3.625 R46.1@18.05,-4.838
  L3 - Signal w0.125: v1(11.7,0.3) 12.1,-0.1 13.625,-0.1 13.775,-0.25 13.775,-0.675 13.65,-0.8 13.05,-0.8 12.925,-0.925 12.925,-1.5 13.025,-1.6 13.575,-1.6 13.7,-1.725 13.7,-2.075 13.8,-2.175 14.825,-2.175 14.925,-2.075 14.925,-1.5 15.05,-1.375 15.4,-1.375 15.525,-1.5 15.525,-2.25 15.625,-2.35 15.975,-2.35 16.1,-2.225 16.1,-1.65 16.2,-1.55 v1(16.8,-1.55)
QSPI1_IO3_PB10: R40.1 R47.1 R50.1 U2.G6 | length 19.6
  L1 - Top w0.125: v1(8.625,-4.25) 8.625,-6.35 9.55,-7.275 R50.1@9.55,-7.525 10.15,-7.525 ; R40.1@10.15,-7.875 10.15,-7.525 ; R47.1@10.15,-7.15 10.15,-7.525 ; v1(10.9,5.1) U2.G6@11.3,4.7 U2.G6@11.35,4.7
  L3 - Signal w0.125: v1(8.625,-4.25) 8.625,-3.6 7.7,-2.675 7.7,-1.175 7.225,-0.7 7.225,5.25 7.475,5.5 8.9,5.5 9.3,5.1 v1(10.9,5.1)
QSPI1_SCK_PB5: R41.1 R48.1 R49.1 U2.A7 | length 16.2
  L1 - Top w0.125: R48.1@9.625,-5.15 R49.1@9.025,-5.15 R41.1@9.025,-4.55 9.025,-3.95 8.925,-3.85 8.275,-3.85 8.175,-3.95 8.175,-4.4 8.35,-4.575 8.35,-6.025 8.275,-6.1 7.65,-6.1 7.575,-6.025 7.575,-3.675 7.7,-3.55 8.95,-3.55 9.05,-3.45 9.05,-2.925 9.2,-2.775 9.45,-2.775 9.6,-2.925 9.6,-3.05 9.7,-3.15 10.3,-3.15 10.4,-3.05 10.4,-1.825 10.3,-1.725 10.15,-1.725 10.05,-1.625 10.05,-1.25 10.15,-1.15 10.525,-1.15 10.625,-1.05 10.625,-0.8 10.525,-0.7 10.2,-0.7 10.1,-0.6 10.1,-0.2 10.2,-0.1 U2.A7@10.5,-0.1
RTC_OUT_PB13: U2.C4 U4.20 | length 17.1
  L1 - Top w0.1: U2.C4@12.9,1.5 v1(13.3,1.1)
  L1 - Top w0.125: U4.20@3.63,-8.6 5.925,-8.6 6.7,-7.825 v1(7.625,-7.825)
  L6 - Bottom w0.125: v1(7.625,-7.825) 8.175,-7.825 8.8,-7.2 8.8,-5.15 11.175,-2.775 11.175,-0.375 11.45,-0.1 11.925,-0.1 12.1,0.075 12.1,0.5 12.3,0.7 12.9,0.7 v1(13.3,1.1)
RTS_WILC_PA25: U2.W18 U4.10 | length 37.7
  L1 - Top w0.125: v1(-1.95,-18.375) U4.10@-1.95,-17.14 ; v1(1.3,14.7) U2.W18@1.7,14.3
  L3 - Signal w0.125: v1(-1.95,-18.375) -1.175,-17.6 -1.175,-4.75 -1.525,-4.4 -1.525,3.7 -1.275,3.95 -1.275,13.625 0.175,15.075 0.925,15.075 v1(1.3,14.7)
RXD: U2.R1 U8.134 | length 5.8
  L1 - Top w0.125: U2.R1@15.3,11.1 v1(16,11.1)
  L6 - Bottom w0.125: v1(16,11.1) 17.7,12.8 U8.134@20.4,12.8
RXD_WILC_DBG: U4.17 U8.42 | length 33.4
  L1 - Top w0.125: U4.17@3.63,-12.2 v1(4.875,-12.2)
  L6 - Bottom w0.125: U8.42@-20.4,-14.4 -18.4,-14.4 -17.625,-15.175 -17.625,-17.175 -17.15,-17.65 3.075,-17.65 3.325,-17.4 3.325,-13.75 v1(4.875,-12.2)
RXD_WILC_PA24: U2.W17 U4.9 | length 40.3
  L1 - Top w0.125: v1(-3.15,-18.375) U4.9@-3.15,-17.14 ; v1(2.1,14.7) U2.W17@2.5,14.3
  L3 - Signal w0.125: v1(-3.15,-18.375) -2.6,-18.375 -1.45,-17.225 -1.45,-5.1 -2.4,-4.15 -2.4,-0.775 -1.85,-0.225 -1.85,3.9 -1.55,4.2 -1.55,13.875 -0.1,15.325 1.475,15.325 v1(2.1,14.7)
SCK_QSPI_PB5: R49.2 U8.96 | length 24.9
  L1 - Top w0.125: R49.2@9.025,-5.675 9.025,-5.925 9.275,-6.175 v1(9.275,-6.45)
  L3 - Signal w0.125: v1(9.275,-6.45) 9.825,-5.9 9.825,-5.675 9.6,-5.45 9.075,-5.45 8.775,-5.75 8.775,-9.825 9.925,-10.975 11.6,-10.975 12.075,-10.5 12.075,-9.75 12.2,-9.625 12.8,-9.625 14.625,-11.45 14.625,-13.05 16.3,-14.725 16.925,-14.725 18.25,-16.05 18.25,-16.6 19.25,-17.6 U8.96@20.4,-17.6
SDIO_CLK_WILC_PA22: U2.V17 U4.22 | length 35.1
  L1 - Top w0.125: v1(2.1,13.9) U2.V17@2.5,13.5 ; U4.22@3.63,-6.2 5.55,-6.2 5.725,-6.375 v1(5.725,-6.7)
  L3 - Signal w0.125: v1(2.1,13.9) 2.5,13.5 3.125,13.5 3.3,13.325 3.3,6.55 2.675,5.925 2.675,0.725 2.275,0.325 2.275,-7.825 3.45,-9 5.25,-9 5.4,-8.85 5.4,-8.225 5.25,-8.075 3.975,-8.075 3.775,-7.875 3.775,-6.9 3.975,-6.7 v1(5.725,-6.7)
SDIO_CMD_WILC_PA28: R32.1 U2.U13 U4.23 | length 35.1
  L1 - Top w0.125: U4.23@3.63,-5 v1(5.775,-5) ; U2.U13@5.7,12.7 v1(6.1,12.3)
  L3 - Signal w0.125: v1(5.775,-5) 5.775,-4.925 6.15,-4.55 6.15,-4.05 5.825,-3.725 4.075,-3.725 3.725,-4.075 3.725,-5.1 4.075,-5.45 5.975,-5.45 6.1,-5.575 6.1,-6.2 6,-6.3 2.85,-6.3 2.65,-6.1 2.65,-1.925 3.075,-1.5 4.125,-1.5 4.5,-1.125 4.5,9.175 4.9,9.575 4.9,11.725 5.075,11.9 5.7,11.9 v1(6.1,12.3)
SDIO_DAT0_WILC_PA18: R31.1 U2.V19 U4.24 | length 35.1
  L1 - Top w0.125: v1(0.4,13.5) U2.V19@0.9,13.5 ; v1(3.5,-2.475) 4.275,-2.475 5.2,-3.4 R31.1@5.2,-3.788 ; U4.24@3.63,-3.8 R31.1@5.2,-3.8
  L3 - Signal w0.125: v1(0.4,13.5) 0.4,14.125 0.575,14.3 2.4,14.3 2.775,13.925 3.725,13.925 4.1,14.3 4.725,14.3 4.9,14.125 4.9,12.85 5.05,12.7 6.25,12.7 6.5,12.45 6.5,11.325 5.975,10.8 5.975,8.125 5.675,7.825 5.225,7.825 4.875,7.475 4.875,-1 5.075,-1.2 5.7,-1.2 5.875,-1.375 5.875,-1.75 5.7,-1.925 5.025,-1.925 4.875,-2.075 4.875,-2.375 5.075,-2.575 5.7,-2.575 5.875,-2.75 5.875,-3.125 5.7,-3.3 3.8,-3.3 3.5,-3 v1(3.5,-2.475)
SDIO_DAT1_WILC_PA19: R30.1 U2.V15 U4.25 | length 35.1
  L1 - Top w0.125: U4.25@1.65,-2.46 1.65,-0.775 1.85,-0.575 4.475,-0.575 5.2,-1.3 5.2,-2.225 5.4,-2.425 6.125,-2.425 6.2,-2.5 R30.1@6.2,-2.763 6.163,-2.8 5.175,-2.8 4.325,-1.95 3.05,-1.95 2.85,-1.75 2.85,-1.225 3.05,-1.025 v1(3.7,-1.025) ; v1(3.7,13.1) U2.V15@4.1,13.5
  L3 - Signal w0.125: v1(3.7,-1.025) 2.85,-1.025 2.65,-0.825 2.65,-0.325 2.85,-0.125 4,-0.125 4.15,0.025 4.15,1.425 4,1.575 3.175,1.575 3.05,1.7 3.05,2.075 3.2,2.225 3.925,2.225 4.1,2.4 4.1,2.95 3.925,3.125 3.2,3.125 3.05,3.275 3.05,3.725 3.2,3.875 3.925,3.875 4.1,4.05 4.1,5.05 3.95,5.2 3.4,5.2 3.15,5.45 3.15,5.95 3.5,6.3 3.925,6.3 4.1,6.475 4.1,12.7 v1(3.7,13.1)
SDIO_DAT2_WILC_PA20: R29.1 U2.T10 U4.26 | length 35.1
  L1 - Top w0.125: v1(-3.85,-0.575) R29.1@-3.35,-0.575 -0.075,-0.575 0.45,-1.1 U4.26@0.45,-2.46 ; v1(7.7,11.5) U2.T10@8.1,11.9
  L3 - Signal w0.125: v1(-3.85,-0.575) -3.85,0 -3.475,0.375 -3.475,2.925 -3.3,3.1 -3.3,12.55 -3,12.85 -3,13.775 -0.825,15.95 3.1,15.95 4.375,14.675 5.075,14.675 5.575,14.175 5.575,13.825 6.7,12.7 7.075,12.7 7.3,12.475 7.3,12.175 7.7,11.775 v1(7.7,11.5)
SDIO_DAT3_WILC_PA21: R28.1 U2.U19 U4.27 | length 35.1
  L1 - Top w0.125: U4.27@-0.75,-2.46 -0.738,-2.448 R28.1@-0.738,-0.95 v1(-0.325,-0.95) ; U2.U19@0.9,12.7 v1(1.3,12.3)
  L3 - Signal w0.125: v1(-0.325,-0.95) -0.325,-3.6 -0.2,-3.725 -0.05,-3.725 0.075,-3.85 0.075,-8.45 0.225,-8.6 1.25,-8.6 1.4,-8.45 1.4,-1.125 1.25,-0.975 0.35,-0.975 0,-0.625 0,6.5 0.275,6.775 1.475,6.775 1.7,7 1.7,11.9 v1(1.3,12.3)
SHDN: R3.1 U2.P4 U8.10 | length 54.7
  L1 - Top w0.125: U8.10@-20.4,11.2 -18.95,11.2 -18.65,10.9 -18.65,9.625 -18.175,9.15 R3.1@-17.525,9.15 ; U2.P4@12.9,10.3 v1(13.3,10.7)
  L3 - Signal w0.125: U8.10@-20.4,11.2 -19.025,11.2 -18.65,11.575 -18.65,17.525 -17.65,18.525 9.275,18.525 10.525,17.275 10.525,16.25 10.9,15.875 13.5,15.875 14.525,14.85 14.525,12.825 14.9,12.45 14.9,10.925 14.275,10.3 13.7,10.3 v1(13.3,10.7)
SIO0_QSPI_PB7: R53.2 U8.98 | length 20.6
  L1 - Top w0.125: v1(10.15,-4.45) R53.2@10.15,-4.012
  L3 - Signal w0.125: v1(10.15,-4.45) 10.5,-4.8 10.5,-10.125 10.725,-10.35 11.275,-10.35 11.45,-10.175 11.45,-9.55 11.875,-9.125 13.075,-9.125 15.3,-11.35 15.3,-11.775 16.025,-12.5 16.325,-12.5 18.25,-14.425 18.25,-15.125 19.125,-16 U8.98@20.4,-16
SIO1_QSPI_PB8: R52.2 U8.99 | length 17.8
  L1 - Top w0.125: R52.2@18.1,-12.387 17.313,-12.387 17.2,-12.5 17.2,-12.85 17.3,-12.95 18.35,-12.95 18.45,-13.05 18.45,-13.425 18.35,-13.525 17.375,-13.525 17.25,-13.65 17.25,-14.05 17.35,-14.15 18.35,-14.15 18.45,-14.25 18.45,-14.6 18.35,-14.7 17.5,-14.7 17.275,-14.925 17.275,-18.55 17.525,-18.8 18.175,-18.8 18.525,-18.45 18.525,-15.425 18.75,-15.2 U8.99@20.4,-15.2
SIO2_QSPI_PB9: R51.2 U8.100 | length 24.3
  L1 - Top w0.125: R51.2@17.812,-1.55 17.812,0.163 17.6,0.375 16.275,0.375 16.175,0.475 16.175,0.65 16.275,0.75 16.7,0.75 17.075,1.125 17.55,1.125 18.45,0.225 18.45,-1.875 18.375,-1.95 17.7,-1.95 17.625,-2.025 17.625,-3.125 17.7,-3.2 18.35,-3.2 18.45,-3.3 18.45,-7.375 18.75,-7.675 18.75,-14.275 18.875,-14.4 U8.100@20.4,-14.4
SIO3_QSPI_PB10: R50.2 U8.97 | length 21.5
  L1 - Top w0.125: v1(9.55,-8.55) R50.2@9.55,-8.05
  L3 - Signal w0.125: v1(9.55,-8.55) 9.55,-6.825 9.65,-6.725 10.025,-6.725 10.125,-6.825 10.125,-10.55 10.225,-10.65 11.475,-10.65 11.75,-10.375 11.75,-9.675 12.05,-9.375 12.925,-9.375 14.975,-11.425 14.975,-12.875 16.475,-14.375 17,-14.375 19.425,-16.8 U8.97@20.123,-16.8
TWCK_ECC608_PD22: R42.1 U2.N6 U6.6 | length 19.6
  L1 - Top w0.1: U2.N6@11.3,9.5 v1(11.7,9.9)
  L1 - Top w0.125: R42.1@-4.725,9.4 -4.375,9.4 -4.25,9.275 v1(-4.25,8.975) U6.6@-4.25,8.398
  L4 - Signal w0.125: v1(-4.25,8.975) -3.85,8.575 -1.475,8.575 -0.55,9.5 7.65,9.5 8.45,8.7 11.075,8.7 11.3,8.925 11.3,9.5 v1(11.7,9.9)
TWCK_MCP16502_PD20: R16.2 U1.6 | length 15
  L1 - Top w0.1: v1(-5.875,10.5) R16.2@-5.425,10.5
  L1 - Top w0.125: v1(-16.875,10.15) U1.6@-15.6,10.15
  L4 - Signal w0.125: v1(-16.875,10.15) -15.525,8.8 -8.9,8.8 -8.5,9.2 -7.95,9.2 -7.625,8.875 -6.375,8.875 -5.875,9.375 v1(-5.875,10.5)
  L6 - Bottom w0.1: v1@-16.95,10.125 -16.925,10.15 v1(-16.875,10.15)
TWCK_SOM_PD20: R18.2 U8.122 | length 7.3
  L1 - Top w0.125: R18.2@18.037,8.725 18.425,8.725 18.6,8.55 18.6,7.3 19.1,6.8 19.1,3.5 19.4,3.2 U8.122@20.4,3.2
TWD_ECC608_PD21: R43.1 U2.P3 U6.5 | length 32.1
  L1 - Top w0.1: U2.P3@13.7,10.3 v1(14.1,10.7)
  L1 - Top w0.125: R43.1@-4.725,9.95 -4.35,9.95 -3.7,9.3 v1(-3.7,8.975) -3.75,8.925 U6.5@-3.75,8.398
  L3 - Signal w0.125: v1(-3.7,8.975) -3.7,11.4 -4.425,12.125 -4.425,13.525 -1.425,16.525 4.675,16.525 5.725,15.475 7.125,15.475 8.3,14.3 13.45,14.3 13.7,14.05 13.7,12.825 13.825,12.7 14.213,12.7 14.525,12.388 14.525,11.125 v1(14.1,10.7)
TWD_MCP16502_PD19: R15.2 U1.5 | length 14.7
  L1 - Top w0.1: v1(-5.875,11.1) R15.2@-5.425,11.1
  L1 - Top w0.125: v1(-16.4,10.65) U1.5@-15.6,10.65
  L4 - Signal w0.125: v1(-16.4,10.65) -16.4,10.125 -15.35,9.075 -9,9.075 -8.6,9.475 -7.8,9.475 -7.475,9.15 -6.55,9.15 -6.25,9.45 -6.25,10.725 v1(-5.875,11.1)
  L6 - Bottom w0.1: v1(-16.4,10.65) -16.35,10.65 v1@-16.325,10.625
TWD_SOM_PD19: R17.2 U8.120 | length 2
  L1 - Top w0.125: R17.2@18.775,2.138 18.775,1.8 18.975,1.6 U8.120@20.4,1.6
TXD_WILC_DBG: U4.16 U8.43 | length 32.9
  L1 - Top w0.125: U4.16@3.63,-13.4 3.755,-13.275 v1(4.875,-13.275)
  L6 - Bottom w0.125: U8.43@-20.4,-15.2 -18.175,-15.2 -17.925,-15.45 -17.925,-17.4 -17.4,-17.925 3.275,-17.925 3.6,-17.6 3.6,-13.95 4.275,-13.275 v1(4.875,-13.275)
TXD_WILC_PA23: U2.U18 U4.8 | length 40.6
  L1 - Top w0.125: v1(-4.35,-18.375) U4.8@-4.35,-17.14 ; v1(-2.55,13.5) -1.8,13.5 -1.4,13.1 1.3,13.1 U2.U18@1.7,12.7
  L3 - Signal w0.125: v1(-4.35,-18.375) -3.775,-18.375 -3.3,-17.9 -2.675,-17.9 -1.725,-16.95 -1.725,-5.325 -2.775,-4.275 -2.775,-0.575 -2.175,0.025 -2.175,4.075 -1.825,4.425 -1.825,12.125 -2.55,12.85 v1(-2.55,13.5)
USBA_N: U2.V7 U8.151 | length 7.3
  L1 - Top w0.125: U2.V7@10.5,13.5 10.9,13.9 10.9,14.45 10.825,14.525 10.825,18.765 10.962,18.903 10.962,20.162 U8.151@11.2,20.4
USBA_P: U2.W7 U8.152 | length 7.2
  L1 - Top w0.125: U8.152@10.4,20.4 10.637,20.163 10.637,19.425 10.562,19.35 10.025,19.35 9.925,19.25 9.925,19.075 10.15,18.85 10.425,18.85 10.5,18.775 U2.W7@10.5,14.3
USBB_N: U2.V8 U8.153 | length 7.5
  L1 - Top w0.125: U8.153@9.6,20.4 9.362,20.162 9.362,19.138 10.025,18.475 10.025,14.528 10.1,14.453 10.1,13.9 U2.V8@9.7,13.5
USBB_P: U2.W8 U8.154 | length 7.4
  L1 - Top w0.125: U8.154@8.8,20.4 9.025,20.175 9.025,19.35 8.95,19.275 8.65,19.275 8.55,19.175 8.55,18.85 8.65,18.75 9.29,18.75 9.7,18.34 U2.W8@9.7,14.3
VBAT: C91.2 C92.2 FB3.2 TP11.1 U4.18 | length 3.4
  L1 - Top w0.4: v1(5.175,-14.25) 5.475,-14.25 5.65,-14.075 FB3.2@5.65,-13.45
  L1 - Top w0.6: FB3.2@5.65,-13.45 C91.2@5.65,-12.05
  L6 - Bottom w0.4: TP11.1@4.35,-14.25 v1(5.175,-14.25)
